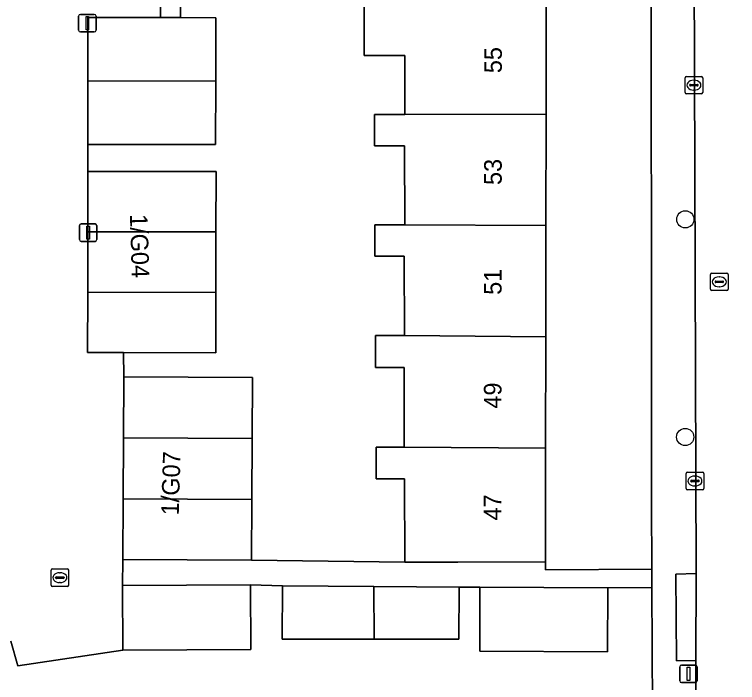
# Model space of a CAD drawing. Extents: x 160732 to 162107, y 387428 to 388479.
# Drawn here: x 161117.3 to 161158.48, y 388160.04 to 388198.11 of the extents above; entities that cross this region are included whole.
import ezdxf

# ---------------------------------------------------------------- set-up
doc = ezdxf.new("R2010")
doc.units = 0
for name, color, linetype in [('IMGEO_Boom', 7, 'Continuous'), ('IMGEO_Erf', 7, 'Continuous'), ('IMGEO_Kolk', 7, 'Continuous'), ('IMGEO_Lichtmast', 7, 'Continuous'), ('IMGEO_Muur', 7, 'Continuous'), ('IMGEO_Pand', 7, 'Continuous'), ('IMGEO_Pand_nummerreeks', 7, 'Continuous'), ('IMGEO_Rijbaan_lokaal_open', 7, 'Continuous'), ('IMGEO_Rioolput', 7, 'Continuous'), ('IMGEO_Voetpad_open', 7, 'Continuous')]:
    doc.layers.add(name, color=color, linetype=linetype)

msp = doc.modelspace()

# ---------------------------------------------------------------- linework, layer by layer
at = {"layer": 'IMGEO_Boom'}
for centre in [(161155.509, 388186.433), (161155.504, 388174.033)]:
    msp.add_circle(centre, 0.489, dxfattribs=at)
at = {"layer": 'IMGEO_Erf'}
for points in [[(161147.583, 388198.758), (161147.576, 388192.42), (161147.569, 388186.082), (161147.562, 388179.744), (161147.554, 388173.406), (161147.547, 388166.913), (161147.549, 388166.47), (161153.606, 388166.499), (161153.588, 388170.261), (161153.568, 388207.782)], [(161126.67, 388204.965), (161126.762, 388197.927), (161128.764, 388197.926), (161128.762, 388194.312), (161128.76, 388190.702), (161121.48, 388190.706), (161121.484, 388189.17), (161128.784, 388189.159), (161128.779, 388185.717), (161128.774, 388182.274), (161128.769, 388178.832), (161123.516, 388178.839), (161123.524, 388177.455), (161130.859, 388177.417), (161130.841, 388173.949), (161130.823, 388170.481), (161130.805, 388167.013), (161139.526, 388166.907), (161139.522, 388171.653), (161137.903, 388171.652), (161137.902, 388173.461), (161139.504, 388173.462), (161139.5, 388178.001), (161137.867, 388178), (161137.866, 388179.82), (161139.507, 388179.822), (161139.504, 388184.336), (161137.833, 388184.334), (161137.831, 388186.123), (161139.527, 388186.125), (161139.524, 388190.619), (161137.802, 388190.617), (161137.801, 388192.417), (161139.531, 388192.418), (161139.529, 388195.773), (161137.221, 388195.776), (161137.225, 388198.771)], [(161153.611, 388165.456), (161151.102, 388165.444), (161151.084, 388161.796), (161143.797, 388161.831), (161143.815, 388165.479), (161142.636, 388165.47), (161142.614, 388162.52), (161137.779, 388162.517), (161132.552, 388162.513), (161132.575, 388165.546), (161130.743, 388165.609), (161130.76, 388161.925), (161123.475, 388161.891), (161117.499, 388160.997), (161117.103, 388162.395)], [(161153.729, 388141.259), (161153.611, 388165.456)]]:
    msp.add_lwpolyline(points, dxfattribs=at)
at = {"layer": 'IMGEO_Kolk'}
for p, q in [((161155.497, 388193.654), (161155.497, 388194.506)), ((161155.572, 388194.58), (161156.424, 388194.58)), ((161155.985, 388194.36), (161156.01, 388194.36)), ((161156.498, 388194.506), (161156.498, 388193.654)), ((161155.756, 388194.074), (161155.756, 388194.086)), ((161156.194, 388194.037), (161155.796, 388194.037)), ((161155.799, 388194.123), (161156.197, 388194.123)), ((161156.24, 388194.086), (161156.24, 388194.074)), ((161156.424, 388193.58), (161155.572, 388193.58)), ((161156.008, 388193.8), (161155.983, 388193.8)), ((161155.556, 388171.098), (161155.556, 388171.95)), ((161155.631, 388172.024), (161156.483, 388172.024)), ((161156.044, 388171.804), (161156.069, 388171.804)), ((161156.557, 388171.95), (161156.557, 388171.098)), ((161155.815, 388171.518), (161155.815, 388171.53)), ((161156.253, 388171.481), (161155.855, 388171.481)), ((161155.858, 388171.567), (161156.256, 388171.567)), ((161156.067, 388171.244), (161156.042, 388171.244)), ((161156.299, 388171.53), (161156.299, 388171.518)), ((161156.483, 388171.024), (161155.631, 388171.024)), ((161119.387, 388165.594), (161119.387, 388166.446)), ((161119.462, 388166.52), (161120.314, 388166.52)), ((161119.875, 388166.3), (161119.9, 388166.3)), ((161120.388, 388166.446), (161120.388, 388165.594)), ((161119.646, 388166.014), (161119.646, 388166.026)), ((161120.084, 388165.977), (161119.686, 388165.977)), ((161119.689, 388166.063), (161120.087, 388166.063)), ((161120.13, 388166.026), (161120.13, 388166.014)), ((161120.314, 388165.52), (161119.462, 388165.52)), ((161119.898, 388165.74), (161119.873, 388165.74))]:
    msp.add_line(p, q, dxfattribs=at)
for points in [[(161155.497, 388193.654), (161155.497, 388194.506)], [(161155.572, 388194.58), (161156.424, 388194.58)], [(161156.498, 388194.506), (161156.498, 388193.654)], [(161156.424, 388193.58), (161155.572, 388193.58)], [(161155.556, 388171.098), (161155.556, 388171.95)], [(161155.631, 388172.024), (161156.483, 388172.024)], [(161156.557, 388171.95), (161156.557, 388171.098)], [(161156.483, 388171.024), (161155.631, 388171.024)], [(161119.387, 388165.594), (161119.387, 388166.446)], [(161119.462, 388166.52), (161120.314, 388166.52)], [(161120.388, 388166.446), (161120.388, 388165.594)], [(161120.314, 388165.52), (161119.462, 388165.52)]]:
    msp.add_lwpolyline(points, dxfattribs=at)
for centre, radius, start, end in [((161155.574, 388194.504), 0.0765, 91.552, 178.448), ((161155.574, 388194.504), 0.0765, 91.552, 178.448), ((161156.422, 388194.504), 0.0765, 1.552, 88.448), ((161156.422, 388194.504), 0.0765, 1.552, 88.448), ((161155.796, 388194.083), 0.0403, 85.8775, 175.7526), ((161155.793, 388194.073), 0.0366, 178.938, 274.7102), ((161156.197, 388194.08), 0.043, 264.8664, 352.4533), ((161156.201, 388194.085), 0.0386, 1.7309, 96.639), ((161155.574, 388193.656), 0.0765, 181.552, 268.448), ((161155.574, 388193.656), 0.0765, 181.552, 268.448), ((161156.422, 388193.656), 0.0765, 271.552, 358.448), ((161156.422, 388193.656), 0.0765, 271.552, 358.448), ((161155.633, 388171.948), 0.0765, 91.552, 178.448), ((161155.633, 388171.948), 0.0765, 91.552, 178.448), ((161156.481, 388171.948), 0.0765, 1.552, 88.448), ((161156.481, 388171.948), 0.0765, 1.552, 88.448), ((161155.855, 388171.527), 0.0403, 85.8775, 175.7526), ((161155.852, 388171.517), 0.0366, 178.938, 274.7102), ((161156.256, 388171.524), 0.043, 264.8664, 352.4533), ((161156.26, 388171.529), 0.0386, 1.7309, 96.639), ((161155.633, 388171.1), 0.0765, 181.552, 268.448), ((161155.633, 388171.1), 0.0765, 181.552, 268.448), ((161156.481, 388171.1), 0.0765, 271.552, 358.448), ((161156.481, 388171.1), 0.0765, 271.552, 358.448), ((161119.464, 388166.444), 0.0765, 91.552, 178.448), ((161119.464, 388166.444), 0.0765, 91.552, 178.448), ((161120.312, 388166.444), 0.0765, 1.552, 88.448), ((161120.312, 388166.444), 0.0765, 1.552, 88.448), ((161119.686, 388166.023), 0.0403, 85.8775, 175.7526), ((161119.683, 388166.013), 0.0366, 178.938, 274.7102), ((161120.087, 388166.02), 0.043, 264.8664, 352.4533), ((161120.091, 388166.025), 0.0386, 1.7309, 96.639), ((161119.464, 388165.596), 0.0765, 181.552, 268.448), ((161119.464, 388165.596), 0.0765, 181.552, 268.448), ((161120.312, 388165.596), 0.0765, 271.552, 358.448), ((161120.312, 388165.596), 0.0765, 271.552, 358.448)]:
    msp.add_arc(centre, radius, start, end, dxfattribs=at)
for centre, major_axis, ratio, start_param, end_param in [((161155.984, 388194.08), (-0.387, 0.002), 0.722429, 4.712389, 7.853982), ((161156.009, 388194.08), (-0.39, 0.002), 0.717154, 1.570796, 4.712389), ((161156.043, 388171.524), (-0.387, 0.002), 0.722429, 4.712389, 7.853982), ((161156.068, 388171.524), (-0.39, 0.002), 0.717154, 1.570796, 4.712389), ((161119.874, 388166.02), (-0.387, 0.002), 0.722429, 4.712389, 7.853982), ((161119.899, 388166.02), (-0.39, 0.002), 0.717154, 1.570796, 4.712389)]:
    msp.add_ellipse(centre, major_axis=major_axis, ratio=ratio, start_param=start_param, end_param=end_param, dxfattribs=at)
at = {"layer": 'IMGEO_Lichtmast'}
for p, q in [((161120.956, 388197.21), (161120.956, 388198.01)), ((161120.956, 388198.01), (161120.956, 388197.21)), ((161121.056, 388198.11), (161121.846, 388198.11)), ((161121.846, 388198.11), (161121.056, 388198.11)), ((161121.946, 388198.01), (161121.946, 388197.21)), ((161121.946, 388197.21), (161121.946, 388198.01)), ((161121.846, 388197.11), (161121.056, 388197.11)), ((161121.056, 388197.11), (161121.846, 388197.11)), ((161121.001, 388185.28), (161121.001, 388186.08)), ((161121.001, 388186.08), (161121.001, 388185.28)), ((161121.101, 388186.18), (161121.891, 388186.18)), ((161121.891, 388186.18), (161121.101, 388186.18)), ((161121.991, 388186.08), (161121.991, 388185.28)), ((161121.991, 388185.28), (161121.991, 388186.08)), ((161121.891, 388185.18), (161121.101, 388185.18)), ((161121.101, 388185.18), (161121.891, 388185.18)), ((161155.192, 388160.142), (161155.192, 388160.942)), ((161155.192, 388160.942), (161155.192, 388160.142)), ((161155.292, 388161.042), (161156.082, 388161.042)), ((161156.082, 388161.042), (161155.292, 388161.042)), ((161156.182, 388160.942), (161156.182, 388160.142)), ((161156.182, 388160.142), (161156.182, 388160.942)), ((161156.082, 388160.042), (161155.292, 388160.042)), ((161155.292, 388160.042), (161156.082, 388160.042))]:
    msp.add_line(p, q, dxfattribs=at)
for points in [[(161121.376, 388197.985), (161121.526, 388197.985), (161121.526, 388197.235), (161121.376, 388197.235), (161121.376, 388197.985)], [(161121.421, 388186.055), (161121.571, 388186.055), (161121.571, 388185.305), (161121.421, 388185.305), (161121.421, 388186.055)], [(161155.612, 388160.917), (161155.762, 388160.917), (161155.762, 388160.167), (161155.612, 388160.167), (161155.612, 388160.917)]]:
    msp.add_lwpolyline(points, dxfattribs=at)
for centre, start, end in [((161121.056, 388198.01), 90, 180), ((161121.056, 388198.01), 90, 180), ((161121.846, 388198.01), 0, 90), ((161121.846, 388198.01), 360, 90), ((161121.056, 388197.21), 180, 270), ((161121.056, 388197.21), 180, 270), ((161121.846, 388197.21), 270, 0), ((161121.846, 388197.21), 270, 0), ((161121.101, 388186.08), 90, 180), ((161121.101, 388186.08), 90, 180), ((161121.891, 388186.08), 0, 90), ((161121.891, 388186.08), 360, 90), ((161121.101, 388185.28), 180, 270), ((161121.101, 388185.28), 180, 270), ((161121.891, 388185.28), 270, 0), ((161121.891, 388185.28), 270, 0), ((161155.292, 388160.942), 90, 180), ((161155.292, 388160.942), 90, 180), ((161156.082, 388160.942), 0, 90), ((161156.082, 388160.942), 360, 90), ((161155.292, 388160.142), 180, 270), ((161155.292, 388160.142), 180, 270), ((161156.082, 388160.142), 270, 0), ((161156.082, 388160.142), 270, 0)]:
    msp.add_arc(centre, 0.1, start, end, dxfattribs=at)
at = {"layer": 'IMGEO_Muur'}
for points in [[(161126.67, 388204.965), (161126.762, 388197.927)], [(161123.475, 388161.891), (161117.499, 388160.997)]]:
    msp.add_lwpolyline(points, dxfattribs=at)
at = {"layer": 'IMGEO_Pand'}
for points in [[(161147.583, 388198.758), (161139.609, 388198.768), (161137.756, 388198.77), (161137.225, 388198.771), (161137.221, 388195.776), (161139.529, 388195.773), (161139.531, 388192.418), (161147.576, 388192.42)], [(161126.762, 388197.927), (161125.806, 388197.928), (161125.617, 388197.928), (161121.484, 388197.931), (161121.482, 388194.318), (161128.762, 388194.312), (161128.764, 388197.926)], [(161121.48, 388190.706), (161128.76, 388190.702), (161128.762, 388194.312), (161121.482, 388194.318)], [(161139.531, 388192.418), (161137.801, 388192.417), (161137.802, 388190.617), (161139.524, 388190.619), (161139.527, 388186.125), (161147.569, 388186.082), (161147.576, 388192.42)], [(161121.479, 388185.727), (161128.779, 388185.717), (161128.784, 388189.159), (161121.484, 388189.17)], [(161147.562, 388179.744), (161147.569, 388186.082), (161139.527, 388186.125), (161137.831, 388186.123), (161137.833, 388184.334), (161139.504, 388184.336), (161139.507, 388179.822)], [(161121.474, 388182.285), (161128.774, 388182.274), (161128.779, 388185.717), (161121.479, 388185.727)], [(161121.469, 388178.842), (161123.516, 388178.839), (161128.769, 388178.832), (161128.774, 388182.274), (161121.474, 388182.285)], [(161147.554, 388173.406), (161147.562, 388179.744), (161139.507, 388179.822), (161137.866, 388179.82), (161137.867, 388178), (161139.5, 388178.001), (161139.504, 388173.462)], [(161123.506, 388173.987), (161130.841, 388173.949), (161130.859, 388177.417), (161123.524, 388177.455)], [(161123.488, 388170.519), (161130.823, 388170.481), (161130.841, 388173.949), (161123.506, 388173.987)], [(161139.504, 388173.462), (161137.902, 388173.461), (161137.903, 388171.652), (161139.522, 388171.653), (161139.526, 388166.907), (161142.548, 388166.909), (161147.547, 388166.913), (161147.554, 388173.406)], [(161123.47, 388167.051), (161130.805, 388167.013), (161130.823, 388170.481), (161123.488, 388170.519)], [(161123.475, 388161.891), (161130.76, 388161.925), (161130.743, 388165.609), (161123.458, 388165.575)], [(161137.777, 388165.507), (161132.575, 388165.546), (161132.552, 388162.513), (161137.779, 388162.517)], [(161142.636, 388165.47), (161137.777, 388165.507), (161137.779, 388162.517), (161142.614, 388162.52)], [(161151.102, 388165.444), (161143.815, 388165.479), (161143.797, 388161.831), (161151.084, 388161.796)]]:
    msp.add_lwpolyline(points, close=True, dxfattribs=at)
at = {"layer": 'IMGEO_Rijbaan_lokaal_open'}
for points in [[(161117.103, 388162.395), (161117.499, 388160.997), (161123.475, 388161.891), (161123.458, 388165.575), (161123.47, 388167.051), (161123.488, 388170.519), (161123.506, 388173.987), (161123.524, 388177.455), (161123.516, 388178.839), (161121.469, 388178.842), (161121.474, 388182.285), (161121.479, 388185.727), (161121.484, 388189.17), (161121.48, 388190.706), (161121.482, 388194.318), (161121.484, 388197.931), (161125.617, 388197.928), (161125.564, 388227.132)], [(161160.946, 388193.594), (161160.967, 388195.059), (161160.943, 388223.645), (161155.942, 388223.612), (161156.12, 388166.254), (161156.114, 388161.291), (161156.023, 388141.534), (161161.118, 388141.556), (161160.945, 388175.907)]]:
    msp.add_lwpolyline(points, dxfattribs=at)
at = {"layer": 'IMGEO_Rioolput'}
for p, q in [((161156.943, 388182.449), (161156.943, 388183.301)), ((161157.018, 388183.375), (161157.87, 388183.375)), ((161157.944, 388183.301), (161157.944, 388182.449)), ((161157.202, 388182.869), (161157.202, 388182.881)), ((161157.64, 388182.832), (161157.242, 388182.832)), ((161157.245, 388182.918), (161157.643, 388182.918)), ((161157.431, 388183.155), (161157.456, 388183.155)), ((161157.686, 388182.881), (161157.686, 388182.869)), ((161157.87, 388182.375), (161157.018, 388182.375)), ((161157.454, 388182.595), (161157.429, 388182.595))]:
    msp.add_line(p, q, dxfattribs=at)
for points in [[(161156.943, 388182.449), (161156.943, 388183.301)], [(161157.018, 388183.375), (161157.87, 388183.375)], [(161157.944, 388183.301), (161157.944, 388182.449)], [(161157.87, 388182.375), (161157.018, 388182.375)]]:
    msp.add_lwpolyline(points, dxfattribs=at)
for centre, radius, start, end in [((161157.02, 388183.299), 0.0765, 91.552, 178.448), ((161157.02, 388183.299), 0.0765, 91.552, 178.448), ((161157.868, 388183.299), 0.0765, 1.552, 88.448), ((161157.868, 388183.299), 0.0765, 1.552, 88.448), ((161157.242, 388182.878), 0.0403, 85.8775, 175.7526), ((161157.239, 388182.868), 0.0366, 178.938, 274.7102), ((161157.643, 388182.875), 0.043, 264.8664, 352.4533), ((161157.647, 388182.88), 0.0386, 1.7309, 96.639), ((161157.02, 388182.451), 0.0765, 181.552, 268.448), ((161157.02, 388182.451), 0.0765, 181.552, 268.448), ((161157.868, 388182.451), 0.0765, 271.552, 358.448), ((161157.868, 388182.451), 0.0765, 271.552, 358.448)]:
    msp.add_arc(centre, radius, start, end, dxfattribs=at)
for centre, major_axis, ratio, start_param, end_param in [((161157.43, 388182.875), (-0.387, 0.002), 0.722429, 4.712389, 7.853982), ((161157.455, 388182.875), (-0.39, 0.002), 0.717154, 1.570796, 4.712389)]:
    msp.add_ellipse(centre, major_axis=major_axis, ratio=ratio, start_param=start_param, end_param=end_param, dxfattribs=at)
at = {"layer": 'IMGEO_Voetpad_open'}
for points in [[(161126.67, 388204.965), (161126.606, 388209.94), (161126.659, 388211.29), (161126.557, 388216.125), (161126.596, 388217.575), (161126.617, 388224.824), (161126.663, 388227.137), (161125.564, 388227.132), (161125.617, 388197.928), (161125.806, 388197.928), (161126.762, 388197.927)], [(161153.606, 388166.499), (161147.549, 388166.47), (161147.547, 388166.913), (161142.548, 388166.909), (161139.526, 388166.907), (161130.805, 388167.013), (161123.47, 388167.051), (161123.458, 388165.575), (161130.743, 388165.609), (161132.575, 388165.546), (161137.777, 388165.507), (161142.636, 388165.47), (161143.815, 388165.479), (161151.102, 388165.444), (161153.611, 388165.456)], [(161156.12, 388166.254), (161154.974, 388166.212), (161155.002, 388161.286), (161156.114, 388161.291)]]:
    msp.add_lwpolyline(points, close=True, dxfattribs=at)
for points in [[(161156.114, 388161.291), (161155.002, 388161.286), (161154.974, 388166.212), (161156.12, 388166.254), (161155.942, 388223.612), (161153.48, 388224.813), (161153.568, 388207.782), (161153.588, 388170.261), (161153.606, 388166.499), (161153.611, 388165.456), (161153.729, 388141.259), (161154.265, 388136.704)], [(161156.019, 388140.67), (161156.023, 388141.534), (161156.114, 388161.291)]]:
    msp.add_lwpolyline(points, dxfattribs=at)

# ---------------------------------------------------------------- texts
at = {"layer": 'IMGEO_Pand_nummerreeks'}
for s, rotation, p in [('55', 89.9372, (161145.059, 388194.764)), ('53', 89.9351, (161145.051, 388188.392)), ('1/G04', 271.7357, (161123.876, 388186.72)), ('51', 89.9351, (161145.045, 388182.133)), ('49', 89.9351, (161145.037, 388175.648)), ('1/G07', 88.2643, (161126.656, 388169.56)), ('47', 89.9351, (161145.03, 388169.276))]:
    msp.add_text(s, height=1, rotation=rotation, dxfattribs=at).set_placement(p)

doc.saveas('drawing.dxf')
